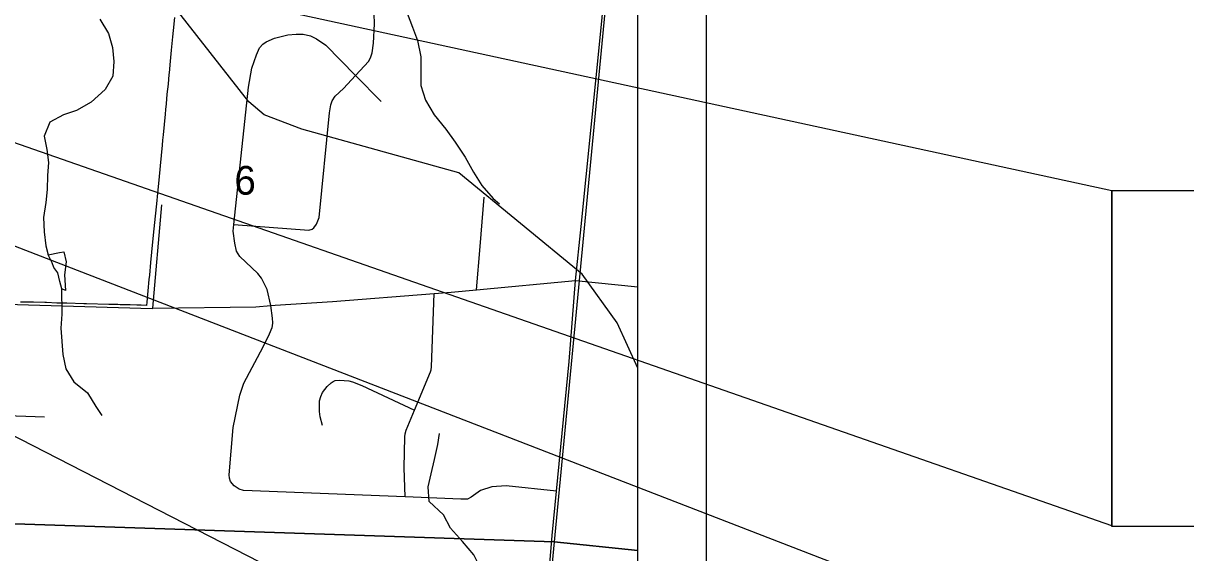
# Model space of a CAD drawing. Extents: x 0 to 34, y -3.9 to 26.2.
# Drawn here: x 8.005 to 9.699, y 15.703 to 16.476 of the extents above; entities that cross this region are included whole.
import ezdxf

# ---------------------------------------------------------------- set-up
doc = ezdxf.new("R2010")
doc.units = 0
for name, color, linetype in [('GM_X_City_Street', 7, 'Continuous'), ('GM_X_Corporation', 7, 'Continuous'), ('GM_X_County_Road', 7, 'Continuous'), ('GM_X_Interchange_Ramps', 7, 'Continuous'), ('GM_X_Interstate_Route', 7, 'Continuous'), ('GM_X_Minor_Lake', 7, 'Continuous'), ('GM_X_Minor_River', 7, 'Continuous'), ('GM_X_Rail_Line', 7, 'Continuous'), ('GM_X_Section', 7, 'Continuous'), ('GM_X_Section_Text', 7, 'Continuous'), ('GM_X_State_Shield', 7, 'Continuous'), ('SH_Data', 7, 'Continuous'), ('SH_Text', 7, 'Continuous')]:
    doc.layers.add(name, color=color, linetype=linetype)

msp = doc.modelspace()

# ---------------------------------------------------------------- linework, layer by layer
at = {"layer": 'GM_X_City_Street'}
for p, q in [((8.1932, 16.0598), (8.2066, 16.2105)), ((7.7886, 15.9108), (8.0353, 15.9016))]:
    msp.add_line(p, q, dxfattribs=at)
for points in [[(8.3116, 16.1821), (8.4207, 16.1738), (8.4258, 16.175), (8.428, 16.1771), (8.432, 16.1823), (8.4357, 16.1921), (8.4508, 16.3448), (8.4526, 16.3566), (8.4549, 16.3624), (8.4591, 16.3693), (8.4711, 16.3804), (8.4888, 16.3994), (8.5083, 16.4204), (8.5111, 16.4264), (8.5128, 16.4324), (8.5151, 16.4465), (8.5166, 16.4745), (8.5159, 16.4894), (8.4954, 16.5774)], [(8.3653, 16.064), (8.3599, 16.0873), (8.3516, 16.1038), (8.3465, 16.1104), (8.3202, 16.1351), (8.3155, 16.1432), (8.3127, 16.1547), (8.3106, 16.1722), (8.3116, 16.1821), (8.3326, 16.3822), (8.3379, 16.4101), (8.3445, 16.4294), (8.3488, 16.4398), (8.3536, 16.4451), (8.3585, 16.4482), (8.3706, 16.4537), (8.3899, 16.4588), (8.4024, 16.4595), (8.4125, 16.4595), (8.4231, 16.4572), (8.4317, 16.4529), (8.4455, 16.4434), (8.4888, 16.3994), (8.5261, 16.3614)], [(8.6652, 16.0867), (8.6704, 16.1497), (8.6761, 16.2221)], [(8.617, 14.1), (8.6198, 14.1232), (8.6255, 14.1764), (8.6256, 14.1778), (8.627, 14.1907), (8.6376, 14.2877), (8.6583, 14.512), (8.664, 14.573), (8.6788, 14.7113), (8.6895, 14.8334), (8.6975, 14.9238), (8.7234, 15.1949), (8.7607, 15.5523), (8.7755, 15.7284), (8.7818, 15.7929), (8.8003, 15.9821), (8.8096, 16.1005)], [(8.561, 15.7846), (8.5598, 15.8269), (8.5607, 15.8725), (8.5613, 15.8768), (8.5628, 15.8819), (8.5749, 15.911), (8.5982, 15.9669), (8.5988, 15.97), (8.5995, 15.9745), (8.6035, 16.0812)], [(8.7818, 15.7929), (8.7084, 15.8009), (8.6875, 15.7996), (8.671, 15.7939), (8.6574, 15.7844), (8.652, 15.7815), (8.6421, 15.7814), (8.561, 15.7846), (8.3254, 15.794), (8.3194, 15.7961), (8.3119, 15.8008), (8.3068, 15.807), (8.3051, 15.812), (8.3047, 15.817), (8.3104, 15.886), (8.32, 15.9329), (8.3262, 15.9506), (8.3542, 16.0034), (8.3635, 16.0226), (8.3671, 16.0316), (8.3677, 16.034), (8.3681, 16.0385), (8.3679, 16.0453), (8.3653, 16.064)], [(8.4408, 15.889), (8.4375, 15.9014), (8.4364, 15.9093), (8.4361, 15.9187), (8.4364, 15.9248), (8.4383, 15.9311), (8.4409, 15.9369), (8.4476, 15.9458), (8.4531, 15.951), (8.4561, 15.953), (8.4589, 15.9543), (8.4656, 15.9552), (8.4722, 15.9547), (8.4789, 15.9539), (8.4842, 15.9525), (8.4978, 15.9472), (8.5749, 15.911)]]:
    msp.add_lwpolyline(points, dxfattribs=at)
at = {"layer": 'GM_X_Corporation'}
msp.add_lwpolyline([(8.2248, 16.4841), (8.223, 16.4651), (8.2221, 16.4556), (8.2202, 16.4364), (8.2187, 16.42), (8.217, 16.4031), (8.2168, 16.4008), (8.2155, 16.3867), (8.214, 16.3719), (8.2127, 16.3581), (8.2119, 16.3495), (8.2113, 16.343), (8.2098, 16.3279), (8.2084, 16.3128), (8.2076, 16.3049), (8.2069, 16.2978), (8.2054, 16.2826), (8.2039, 16.2675), (8.2019, 16.2467), (8.1995, 16.2228), (8.199, 16.2172), (8.1949, 16.1757), (8.1915, 16.1419), (8.1915, 16.1418), (8.1901, 16.1268), (8.1883, 16.1081), (8.1876, 16.1017), (8.1845, 16.0688), (8.184, 16.064), (8.1764, 16.0642), (8.1727, 16.0644), (8.1699, 16.0644), (8.1602, 16.0646), (8.1575, 16.0648), (8.146, 16.065), (8.1424, 16.0651), (8.1405, 16.0652), (8.1388, 16.0652), (8.1294, 16.0655), (8.0965, 16.0663), (8.0953, 16.0664), (8.0927, 16.0664), (8.0681, 16.0671), (8.0669, 16.0671), (8.0593, 16.0673), (8.0566, 16.0674), (8.0535, 16.0674), (8.0385, 16.068), (8.0358, 16.0681), (8.0195, 16.0685), (8.0074, 16.0688), (8.0006, 16.0689)], dxfattribs=at)
at = {"layer": 'GM_X_County_Road'}
for q in [(8.8175, 16.1791), (8.9, 16.0911)]:
    msp.add_line((8.8096, 16.1005), q, dxfattribs=at)
for points in [[(8.8175, 16.1791), (8.8469, 16.4689), (8.8642, 16.6502), (8.871, 16.7248), (8.8843, 16.8672)], [(7.8064, 16.0731), (7.9798, 16.0658), (8.1924, 16.0597), (8.1932, 16.0598), (8.3436, 16.062), (8.3653, 16.064), (8.3718, 16.0645), (8.4554, 16.0695), (8.6035, 16.0812), (8.6281, 16.0832), (8.6652, 16.0867), (8.8096, 16.1005)]]:
    msp.add_lwpolyline(points, dxfattribs=at)
at = {"layer": 'GM_X_Interchange_Ramps'}
for points in [[(7.395, 14.1), (8.9, 14.1), (8.9, 20.3498)], [(8.2248, 16.4841), (8.223, 16.4651), (8.2221, 16.4556), (8.2202, 16.4364), (8.2187, 16.42), (8.217, 16.4031), (8.2168, 16.4008), (8.2155, 16.3867), (8.214, 16.3719), (8.2127, 16.3581), (8.2119, 16.3495), (8.2113, 16.343), (8.2098, 16.3279), (8.2084, 16.3128), (8.2076, 16.3049), (8.2069, 16.2978), (8.2054, 16.2826), (8.2039, 16.2675), (8.2019, 16.2467), (8.1995, 16.2228), (8.199, 16.2172), (8.1949, 16.1757), (8.1915, 16.1419), (8.1915, 16.1418), (8.1901, 16.1268), (8.1883, 16.1081), (8.1876, 16.1017), (8.1845, 16.0688), (8.184, 16.064), (8.1764, 16.0642), (8.1727, 16.0644), (8.1699, 16.0644), (8.1602, 16.0646), (8.1575, 16.0648), (8.146, 16.065), (8.1424, 16.0651), (8.1405, 16.0652), (8.1388, 16.0652), (8.1294, 16.0655), (8.0965, 16.0663), (8.0953, 16.0664), (8.0927, 16.0664), (8.0681, 16.0671), (8.0669, 16.0671), (8.0593, 16.0673), (8.0566, 16.0674), (8.0535, 16.0674), (8.0385, 16.068), (8.0358, 16.0681), (8.0195, 16.0685), (8.0074, 16.0688), (8.0006, 16.0689)]]:
    msp.add_lwpolyline(points, dxfattribs=at)
at = {"layer": 'GM_X_Interstate_Route'}
msp.add_lwpolyline([(2.5468, 14.1), (8.9, 14.1), (8.9, 16.7226), (8.8708, 16.7253), (8.3218, 16.7826), (8.2541, 16.7887), (8.1936, 16.7941), (8.1769, 16.7957), (7.8848, 16.8273)], dxfattribs=at)
at = {"layer": 'GM_X_Minor_Lake'}
msp.add_lwpolyline([(8.0407, 16.1378), (8.0572, 16.1413), (8.0637, 16.1419), (8.0672, 16.1274), (8.0645, 16.1085), (8.0659, 16.0857), (8.0607, 16.088), (8.0578, 16.0987), (8.0551, 16.1113), (8.0491, 16.1194), (8.0466, 16.1263), (8.0407, 16.1378)], dxfattribs=at)
at = {"layer": 'GM_X_Minor_River'}
for points in [[(8.3968, 16.7691), (8.4077, 16.7442), (8.4164, 16.7232), (8.434, 16.7035), (8.4427, 16.6845), (8.458, 16.6635), (8.479, 16.6445), (8.4988, 16.632), (8.5175, 16.611), (8.5144, 16.5886), (8.5217, 16.5696), (8.5422, 16.5506), (8.551, 16.5308), (8.5583, 16.5106), (8.564, 16.4901), (8.5716, 16.4699), (8.5792, 16.4505), (8.5838, 16.4266), (8.5838, 16.4045)], [(8.1162, 16.4814), (8.1287, 16.4604), (8.1348, 16.4399), (8.1364, 16.4197), (8.1349, 16.3981), (8.1238, 16.379), (8.1036, 16.3604), (8.0823, 16.3482), (8.0632, 16.3421), (8.0434, 16.3311), (8.035, 16.311), (8.0388, 16.2916), (8.0415, 16.2725), (8.04, 16.2535), (8.0396, 16.233), (8.0377, 16.214), (8.0343, 16.1923), (8.035, 16.1714), (8.0373, 16.1508), (8.0407, 16.1378)], [(8.5838, 16.4045), (8.5838, 16.3847), (8.5907, 16.3634), (8.6036, 16.3418), (8.6204, 16.3212), (8.6338, 16.3022), (8.6486, 16.2801), (8.6608, 16.2584), (8.673, 16.239), (8.6894, 16.22), (8.6986, 16.212)], [(8.0605, 16.0885), (8.061, 16.0512), (8.0591, 16.031), (8.0621, 15.9922), (8.0667, 15.9717), (8.0785, 15.9523), (8.0983, 15.9363), (8.1105, 15.9165), (8.1189, 15.9032)], [(8.665, 15.5234), (8.6632, 15.543), (8.6552, 15.565), (8.6563, 15.5848), (8.6758, 15.5981), (8.6891, 15.6171), (8.6861, 15.6365), (8.68, 15.6594), (8.6716, 15.6799), (8.6613, 15.7001), (8.6449, 15.7199), (8.6274, 15.7393), (8.6171, 15.7587), (8.5961, 15.7781), (8.5946, 15.7994), (8.5988, 15.8184), (8.6041, 15.8393), (8.6087, 15.861), (8.6113, 15.877)]]:
    msp.add_lwpolyline(points, dxfattribs=at)
at = {"layer": 'GM_X_Rail_Line'}
msp.add_lwpolyline([(8.9, 15.9724), (8.8703, 16.0388), (8.819, 16.1095), (8.6393, 16.2573), (8.4103, 16.3212), (8.3557, 16.3419), (8.3331, 16.3607), (8.2013, 16.5302), (8.1507, 16.5531), (8.1045, 16.5577), (7.961, 16.5433), (7.8546, 16.5443), (7.7534, 16.5507)], dxfattribs=at)
at = {"layer": 'GM_X_Section'}
for points in [[(7.8864, 16.832), (8.8743, 16.7258), (8.7783, 15.7191), (7.7738, 15.7526)], [(8.7783, 15.7191), (8.6823, 14.7132), (7.6773, 14.7406), (7.7738, 15.7526)]]:
    msp.add_lwpolyline(points, close=True, dxfattribs=at)
at = {"layer": 'GM_X_State_Shield'}
for points in [[(8.9, 15.7064), (8.9, 16.7234), (8.8743, 16.7258), (8.7783, 15.7191)], [(8.9, 14.6934), (8.9, 15.7064), (8.7783, 15.7191), (8.6823, 14.7132)]]:
    msp.add_lwpolyline(points, close=True, dxfattribs=at)
at = {"layer": 'SH_Data'}
msp.add_line((9, 21), (9, 14), dxfattribs=at)
at = {"layer": 'SH_Text'}
for points in [[(9.5912, 16.2318), (9.5912, 15.7425), (5.8947, 17.034)], [(9.6746, 15.4992), (9.6746, 15.0088), (5.7921, 17.0032)], [(9.5912, 16.2318), (11.2483, 16.2318), (11.2483, 15.7414), (9.5912, 15.7414)]]:
    msp.add_lwpolyline(points, close=True, dxfattribs=at)

# ---------------------------------------------------------------- texts
at = {"layer": 'GM_X_Section_Text'}
msp.add_text('6', height=0.0419, rotation=0, dxfattribs=at).set_placement((8.3123, 16.2255))

doc.saveas('drawing.dxf')
